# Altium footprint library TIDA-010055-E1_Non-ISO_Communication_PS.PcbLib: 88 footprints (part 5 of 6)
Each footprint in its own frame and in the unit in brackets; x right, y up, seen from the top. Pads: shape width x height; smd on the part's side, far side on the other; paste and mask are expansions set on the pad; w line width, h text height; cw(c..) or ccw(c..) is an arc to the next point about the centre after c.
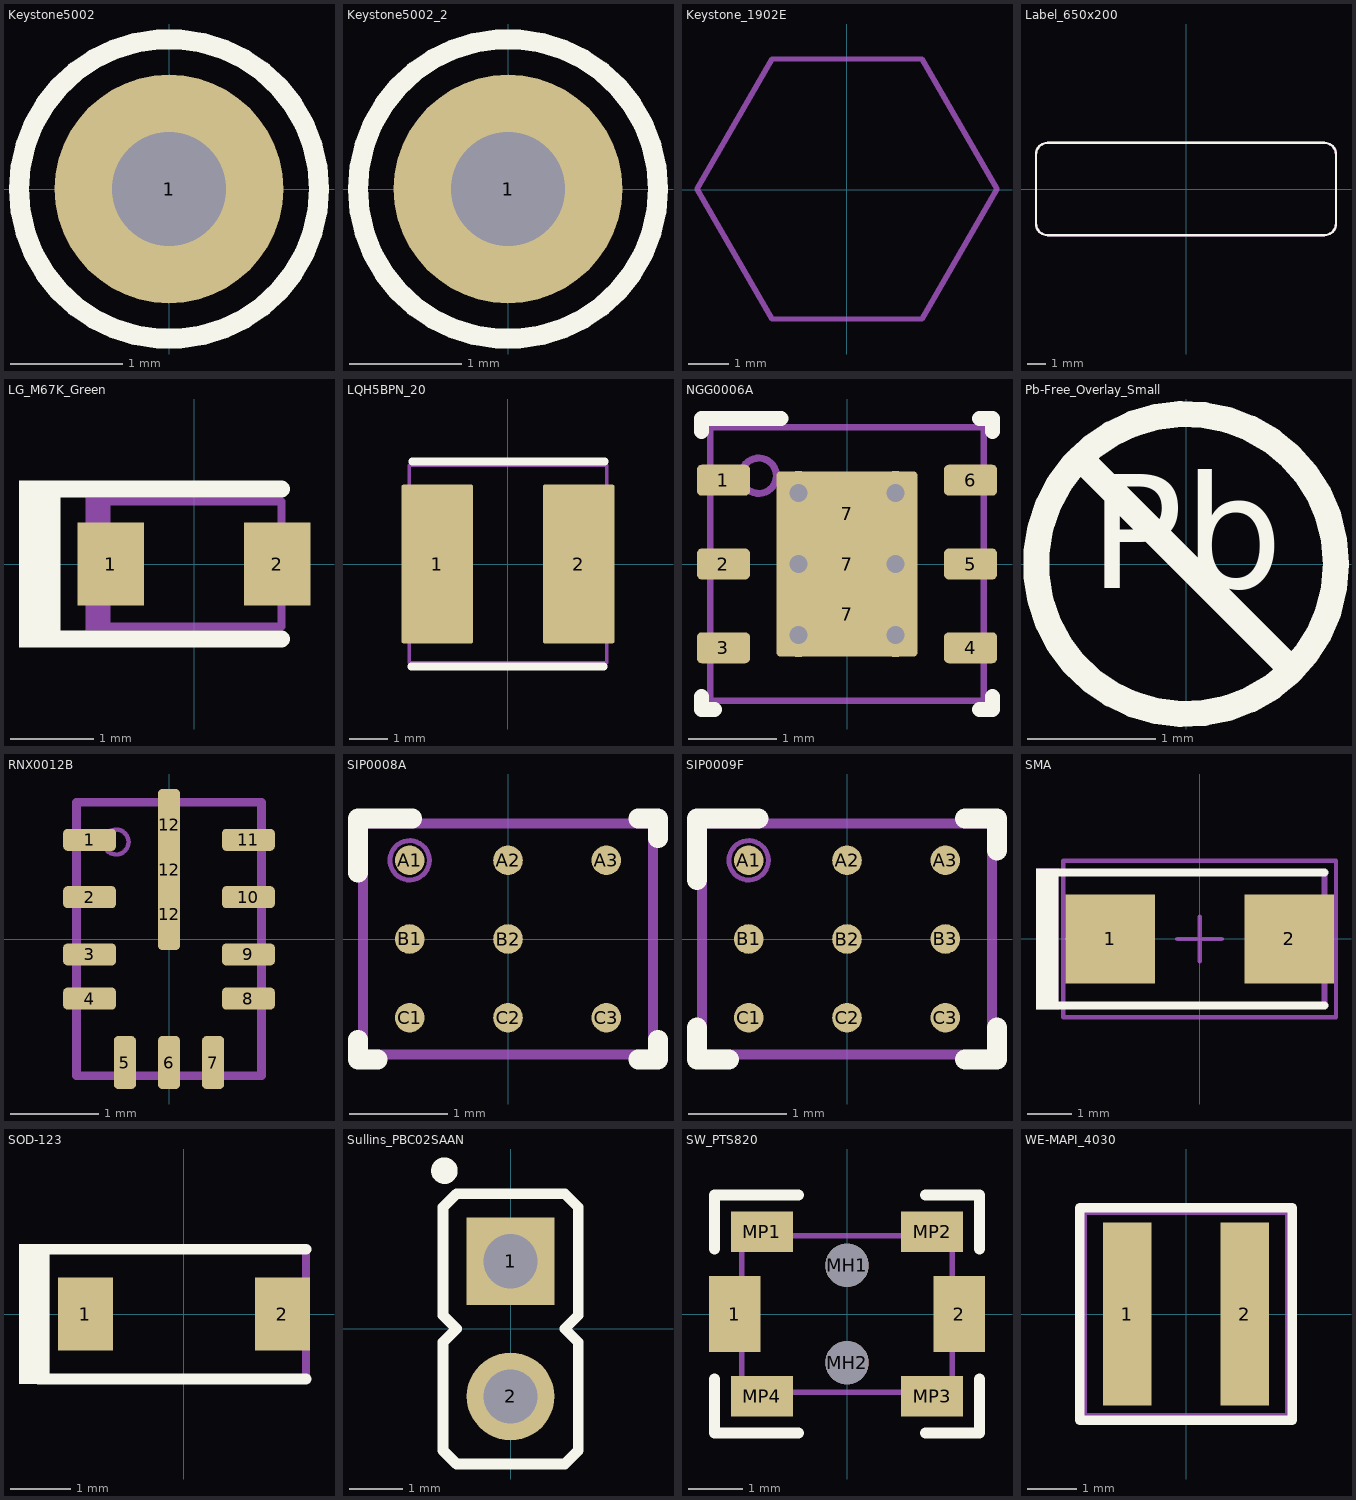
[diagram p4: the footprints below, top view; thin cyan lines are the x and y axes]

## Keystone5002 [mil] "For Keystone 500x miniature loop terminals"
height 181.1
pads (1):
  round 80 hole 40: 1(0,0)
Top Overlay:
  circle w7: c0,0 r52.5
Mechanical 5:
  circle w3.94: c0,0 r52.5
  text ".Designator" at 4.95,23.33 h25
3D body "Keystone_5002.stp": height 181.97, standoff -118.11, extent -49,-49 49.04,49.23

## Keystone5002_2 [mil]
pads (1):
  round 80 hole 40: 1(0,0)
Top Overlay:
  circle w7: c0,0 r52.5
Mechanical 5:
  circle w3.94: c0,0 r52.5
  text ".Designator" at 22,24 h25
3D body "Keystone_5002.stp": height 181.97, standoff -118.11, extent -49,-49 49.04,49.23

## Keystone_1902E [mil] "Hex Standoff, 4-40 threaded, nylon"
height 1000
pads (1):
  round 1 on Mech3: 0(0,0)
Mechanical 5:
  lines w5: -145.29,0.49 -72.56,-125.49 72.92,-125.49 145.65,0.49 72.92,126.47 -72.56,126.47 -145.29,0.49
  text ".Designator" at -60,-20 h25
3D body "Keystone_1902E.stp": height 1001, standoff 1, extent -144.95,-125.98 146,125.98

## Label_650x200 [mil] "Thermal Transfer Label"
height 1
pads (1):
  round 1 on Mech13: 0(0,0)
Top Overlay:
  lines w5: -325,-75 ccw(c-300,-75) -300,-100 300,-100 ccw(c300,-75) 325,-75 325,75 ccw(c300,75) 300,100 -300,100 ccw(c-300,75) -325,75 -325,-75
Mechanical 5:
  lines w5: -325,-75 ccw(c-300,-75) -300,-100 300,-100 ccw(c300,-75) 325,-75 325,75 ccw(c300,75) 300,100 -300,100 ccw(c-300,75) -325,75 -325,-75
  text ".Designator" at -60,-20 h25
3D body: height 1, standoff 0, extent -325.02,-100.02 325.02,100.02

## LG_M67K_Green [mm] "SMD, 2-Leads, Body 2x1.4mm, Pitch 2mm"
height 1.4
pads (2):
  rect 0.8x1 smd mask+0: 1(-1,0) 2(1,0)
Top Overlay:
  rectangle: -2.1,-1 -1.6,1
  lines w0.2: -2,-0.9 1.05,-0.9 ; -2,0.9 1.05,0.9
Mechanical 5:
  rectangle: -1.3,-0.8 -1.05,0.8
  lines w0.1: -1.05,-0.75 -1.05,0.75 1.05,0.75 1.05,-0.75 -1.05,-0.75
  text ".Designator" at -0.584,-0.254 h0.64
3D body: height 0.9, standoff 0.6, extent -0.799,-0.149 -0.6,0.15
3D body: height 1.4, standoff 0, extent -1.049,-0.749 1.049,0.749

## LQH5BPN_20 [mm] "MURATA"
height 2.2
pads (2):
  rrect5% 1.85x4.1 smd: 1(-1.825,0) 2(1.825,0)
Top Overlay:
  lines w0.2: -2.5,-2.65 2.475,-2.65 ; -2.475,2.65 2.5,2.65
Mechanical 5:
  lines w0.1: -2.55,-2.55 2.55,-2.55 2.55,2.55 -2.55,2.55 -2.55,-2.55
  text ".Designator" at 0.064,-0.209 h0.64
3D body: height 2.2, standoff 0, extent -2.549,-2.549 2.549,2.549

## NGG0006A [mm] "TI recommended footprint"
height 0.8
pads (9):
  rrect29% 0.6x0.35 smd: 1(-1.4,0.95) 2(-1.4,0) 3(-1.4,-0.95) 4(1.4,-0.95) 5(1.4,0) 6(1.4,0.95)
  rrect50% 1.47x0.94 on Top Paste: 7(0,-0.57) 7(0,0.57)
  rrect6% 1.6x2.1 smd paste-1: 7(0,0)
via 0.55,0.804 diameter 0.5 hole 0.2
via 0.55,-0.804 diameter 0.5 hole 0.2
via -0.55,-0.804 diameter 0.5 hole 0.2
via -0.55,0.804 diameter 0.5 hole 0.2
via -0.55,0 diameter 0.5 hole 0.2
via 0.55,0 diameter 0.5 hole 0.2
Top Overlay:
  lines w0.17: -1.65,-1.5 -1.65,-1.65 -1.5,-1.65 ; -1.65,1.5 -1.65,1.65 -0.75,1.65 ; 1.5,-1.65 1.65,-1.65 1.65,-1.5 ; 1.5,1.65 1.65,1.65 1.65,1.5
Mechanical 5:
  circle w0.08: c-1,1 r0.2
  lines w0.07: -1.55,-1.55 1.55,-1.55 1.55,1.55 -1.55,1.55 -1.55,-1.55
  text ".Designator" at 0.449,-0.794 h0.64
3D body "NGG0006A.stp": height 0.81, standoff 0.01, extent -1.5,-1.5 1.5,1.5

## Pb-Free_Overlay_Small [mm]
height 3
Top Overlay:
  circle w0.203: c0,0 r1.168
  lines w0.203: -0.826,0.826 0.826,-0.826
  text "Pb" at -0.752,-0.48 h1.52

## RNX0012B [mm] "VQFN-HR-12"
height 1
pads (14):
  rrect40% 0.6x0.25 smd: 1(-0.9,1.125) 2(-0.9,0.475) 3(-0.9,-0.175) 4(-0.9,-0.675) 8(0.9,-0.675) 9(0.9,-0.175) 10(0.9,0.475) 11(0.9,1.125)
  rrect40% 0.25x0.6 smd: 5(-0.5,-1.4) 6(0,-1.4) 7(0.5,-1.4)
  rrect50% 0.25x0.812 on Top Paste: 12(0,0.28) 12(0,1.295)
  rrect40% 0.25x1.825 smd paste-0.175: 12(0,0.788)
Mechanical 5:
  circle w0.05: c-0.6,1.1 r0.141
  lines w0.1: -1.05,-1.55 -1.05,1.55 1.05,1.55 1.05,-1.55 -1.05,-1.55
  text ".Designator" at 0.493,-0.787 h0.64
3D body "RNX0012B.stp": height 1, standoff 0, extent -1,-1.5 1,1.5

## SIP0008A [mm] "SIP, 9-Leads, Body 2.35x2.95mm, Pitch 1mm x 0.8 mm, TI Recommended"
height 1
pads (8):
  round 0.3 smd paste+0.02: A1(-1,0.8) A2(0,0.8) A3(1,0.8) B1(-1,0) B2(0,0) C1(-1,-0.8) C2(0,-0.8) C3(1,-0.8)
Top Overlay:
  lines w0.2: -1.525,-1.025 -1.525,-1.225 -1.325,-1.225 ; -1.525,0.675 -1.525,1.225 -0.975,1.225 ; 1.325,-1.225 1.525,-1.225 1.525,-1.025 ; 1.325,1.225 1.525,1.225 1.525,1.025
Mechanical 5:
  circle w0.05: c-1,0.8 r0.2
  lines w0.1: -1.475,-1.175 -1.475,1.175 1.475,1.175 1.475,-1.175 -1.475,-1.175
  text ".Designator" at -1.2,-0.2 h0.64
3D body "SIP0008A.stp": height 0.93, standoff 0, extent -1.45,-1.15 1.45,1.15

## SIP0009F [mm] "SIP, 9-Leads, Body 2.35x2.95mm, Pitch 1mm x 1.1 mm, TI Recommended"
height 1.1
pads (9):
  round 0.3 smd paste+0.02: A1(-1,0.8) A2(0,0.8) A3(1,0.8) B1(-1,0) B2(0,0) B3(1,0) C1(-1,-0.8) C2(0,-0.8) C3(1,-0.8)
Top Overlay:
  lines w0.2: -1.525,-0.9 -1.525,-1.225 -1.2,-1.225 ; -1.525,0.6 -1.525,1.225 -0.9,1.225 ; 1.2,-1.225 1.525,-1.225 1.525,-0.9 ; 1.2,1.225 1.525,1.225 1.525,0.9
Mechanical 5:
  circle w0.05: c-1,0.8 r0.2
  lines w0.1: -1.475,-1.175 1.475,-1.175 1.475,1.175 -1.475,1.175 -1.475,-1.175
  text ".Designator" at -1.2,-0.3 h0.64
3D body "SIP0009F.stp": height 1.1, standoff 0, extent -1.45,-1.15 1.45,1.15

## SMA [mm] "Molded Diode, 2-Leads, Body 4.3x2.6mm, IPC Medium Density, based on OnSemi component dimensions and land pattern"
height 2.27
pads (2):
  rect 2x2 smd: 1(-2,0) 2(2,0)
Top Overlay:
  rectangle: -3.658,-1.575 -3.15,1.575
  lines w0.178: -3.327,-1.486 2.794,-1.486 ; -3.327,1.486 2.794,1.486
Mechanical 5:
  rectangle: -3.658,-1.575 -3.15,1.575
  lines w0.127: -3.327,-1.486 2.794,-1.486 2.794,1.486 -3.327,1.486
  text ".Designator" at 0.298,0.238 h0.64
Mechanical 15:
  lines w0.1: -0.5,0 0.5,0 ; 0,-0.5 0,0.5 ; -3.05,-1.75 -3.05,1.75 3.05,1.75 3.05,-1.75 -3.05,-1.75
3D body "SMA_nominal.stp": height 2.42, standoff 0.02, extent -2.6,-1.3 2.6,1.3

## SOD-123 [mm] "On Semi recommended land pattern"
height 1.35
pads (2):
  rect 0.915x1.22 smd: 1(-1.637,0) 2(1.637,0)
Top Overlay:
  rectangle: -2.743,-1.168 -2.235,1.169
  lines w0.178: -2.413,-1.079 2.032,-1.079 ; -2.413,1.079 2.032,1.079
Mechanical 5:
  rectangle: -2.743,-1.168 -2.235,1.169
  lines w0.127: -2.413,-1.079 2.032,-1.079 2.032,1.079 -2.413,1.079
  text ".Designator" at -0.533,0.467 h0.64
3D body "SOD-123.stp": height 1.35, standoff 0, extent -1.932,-0.9 1.932,0.9

## Sullins_PBC02SAAN [mm] "Sullins 100mil, 1x2, 230 mil above insulator"
height 8.382
pads (2):
  rect 1.65x1.65 hole 1.016: 1(0,1.27)
  round 1.65 hole 1.016: 2(0,-1.27)
Top Overlay:
  circle w0.25: c-1.245,2.972 r0.125
  lines w0.2: -1.27,-2.286 -1.27,-0.254 -1.016,0 -1.27,0.254 -1.27,2.286 -1.016,2.54 1.016,2.54 1.27,2.286 1.27,0.254 1.016,0 1.27,-0.254 1.27,-2.286 1.016,-2.54 -1.016,-2.54 -1.27,-2.286
Mechanical 5:
  lines w0.1: -1.27,-2.286 -1.016,-2.54 1.016,-2.54 1.27,-2.286 1.27,-0.254 1.016,0 1.27,0.254 1.27,2.286 1.016,2.54 -1.016,2.54 -1.27,2.286 -1.27,0.254 -1.016,0 -1.27,-0.254 -1.27,-2.286
  text ".Designator" at 0.277,-0.361 h0.64
3D body: height 2.54, standoff 0, extent -1.27,-2.54 1.27,2.54
3D body: height 8.38, standoff -3.05, extent -0.317,-1.587 0.317,-0.953
3D body: height 8.38, standoff -3.05, extent -0.317,0.953 0.317,1.587

## SW_PTS820 [mm] "SMT, 2-Leads, Body 3.9x2.9mm"
height 2
pads (8):
  rect 0.95x1.4 smd: 1(-2.075,0) 2(2.075,0)
  round 0.8 hole 0.8 unplated: MH1(0,0.9) MH2(0,-0.9)
  rect 1.15x0.75 smd: MP1(-1.575,1.525) MP2(1.575,1.525) MP3(1.575,-1.525) MP4(-1.575,-1.525)
Top Overlay:
  lines w0.2: -2.45,-1.2 -2.45,-2.2 -0.9,-2.2 ; -2.45,1.2 -2.45,2.2 -0.9,2.2 ; 1.45,-2.2 2.45,-2.2 2.45,-1.2 ; 1.45,2.2 2.45,2.2 2.45,1.2
Mechanical 5:
  lines w0.1: -1.95,-0.5 -1.982,-0.5 -2.157,-0.5 -2.25,-0.5 -2.25,0.5 -2.157,0.5 -1.982,0.5 -1.95,0.5 ; 1.95,-0.5 1.982,-0.5 2.157,-0.5 2.25,-0.5 2.25,0.5 2.157,0.5 1.982,0.5 1.95,0.5 ; -1.95,-1.45 -1.95,1.45 1.95,1.45 1.95,-1.45 -1.95,-1.45
  text ".Designator" at -0.43,0.654 h0.64
3D body "PTS820.stp": height 2, standoff -0.5, extent -2.25,-1.45 2.25,1.45

## WE-MAPI_4030 [mm] "SMD, 2-Leads, Body 4.1x4.1mm"
height 3.1
pads (2):
  rect 0.98x3.7 smd: 1(-1.185,0) 2(1.185,0)
Top Overlay:
  lines w0.2: -2.15,-2.15 -2.15,2.15 2.15,2.15 2.15,-2.15 -2.15,-2.15
Mechanical 5:
  lines w0.1: -2.05,-2.05 2.05,-2.05 2.05,2.05 -2.05,2.05 -2.05,-2.05
  text ".Designator" at -0.66,0.185 h0.64
3D body "4020_3100.stp": height 3.1, standoff 0, extent -2.05,-2.05 2.05,2.05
